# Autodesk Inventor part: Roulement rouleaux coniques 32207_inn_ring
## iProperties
Created: 2000-12
Part Number: Roulement rouleaux coniques 32207_inn_ring
Material: Par défaut
Document SubType Name: Modélisation
Designer: Administrateur
Control State: 0
Master: False
Checked Out: False
Shininess: 20.0
Length Units: 11269
Angle Units: 11279
Time Units: 11290
Mass Units: 11283
Length Display Precision: 3
Angle Display Precision: 2
Density: 0.0
Volumn: 0.0
Area: 0.0
PropertySet Name: Model Information
Author: Administrateur
